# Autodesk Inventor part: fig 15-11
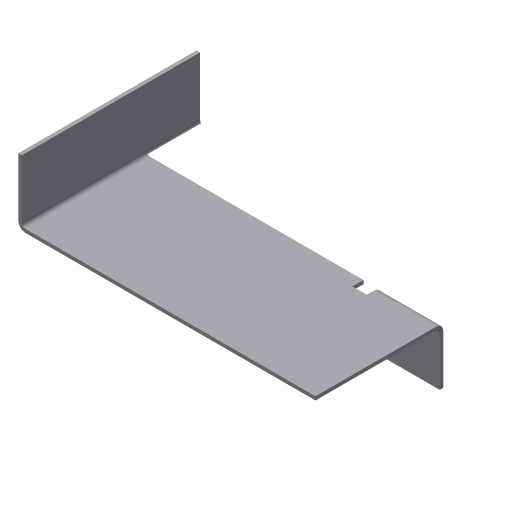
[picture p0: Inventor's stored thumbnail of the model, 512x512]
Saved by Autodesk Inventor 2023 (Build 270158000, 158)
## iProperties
Created: 2002-04
Part Number: fig 15-11
Material: Aluminum-6061
Document SubType Name: Sheet Metal
Density: 1 g/cm^3
Sheet Metal Rule: Default
Appearance: Aluminum - Flat-1
Control State: 0
Master: False
Checked Out: False
Shininess: 77.0
Angle Display Precision: 2
Document Length Units: 11269
Document Angle Units: 11279
Document Time Units: 11290
Document Mass Units: 11283
Document Length Units Precision: 3
Document Angle Units Precision: 2
Density: 0.0
Volumn: 0.0
Area: 0.0
PropertySet Name: Model Information
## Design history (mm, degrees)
node "Face1"
  sketch "Sketch1"
    geometry: L1 (-49.559, 19.574)-(-49.559, -30.426); L2 (-49.559, -30.426)-(50.441, -30.426); L3 (50.441, -30.426)-(50.441, 19.574); L4 (50.441, 19.574)-(32.941, 19.574); L5 (32.941, 19.574)-(32.941, 4.574); L6 (32.941, 4.574)-(-32.059, 4.574); L7 (-32.059, 4.574)-(-32.059, 19.574); L8 (-32.059, 19.574)-(-49.559, 19.574)
    constraints: 16 end point, 6 parallel, 2 equal length, 1 perpendicular, 1 vertical
    dimensions: "d0" = 100 distance of L1.end L2.end; "d1" = 65 distance of L5.end L6.end; "d2" = 15 distance of L6.end L7.end; "d3" = 50 distance of L1.start L1.end
sketch "Sketch2"
  geometry: L1 (100, 0)-(0, 0) reference; L2 (17.5, 50)-(17.5, 35) reference; L3 (82.5, 50)-(82.5, 0)
  constraints: 2 end point, 1 parallel, 1 point on line
sketch "Sketch3"
  geometry: L1 (81.369, -50)-(0, -50) reference; L2 (17.5, 0)-(17.5, -50)
  constraints: 2 end point, 1 perpendicular, 1 point on line
feature "Fold2" sketch "Sketch3" dims "d8" = 1 (= BendRadius), "d9" = 90 deg, "d10" = 1 (= BendRadius), "d14" = 1 (= BendReliefWidth), "d15" = 0.5 (= BendReliefDepth), "d16" = 2 (= MinimumRemnant), "d20" = 1 (= Thickness), "SeamGap" = 0.01
sketch "Sketch4"
  geometry: L1 (17.5, 0)-(17.5, -50) reference; L2 (-63.869, -15)-(0, -15) reference; L3 (0, -15)-(17.5, -15)
  constraints: 2 end point, 1 collinear, 1 point on line
feature "Fold3" sketch "Sketch4" dims "d11" = 1 (= BendRadius), "d12" = 90 deg, "d13" = 1 (= BendRadius), "d17" = 4, "d18" = 2, "d19" = 2 (= MinimumRemnant), "d20" = 1 (= Thickness), "SeamGap" = 0.01
body "Solid1"
face "Plate1" dims "d20" = 1 (= Thickness)
other parameters: "Thickness" = 1, "BendRadius" = 1 (= Thickness), "BendReliefWidth" = 1 (= Thickness), "BendReliefDepth" = 0.5 (= 0.5 x Thickness), "CornerReliefSize" = 4 (= 4 x Thickness), "MinimumRemnant" = 2 (= 2 x Thickness), "TransitionRadius" = 1 (= BendRadius), "d4" = 1 (= BendRadius), "JacobiRadiusSize" = 1 (= Thickness), "GapSize" = 1 (= Thickness)
